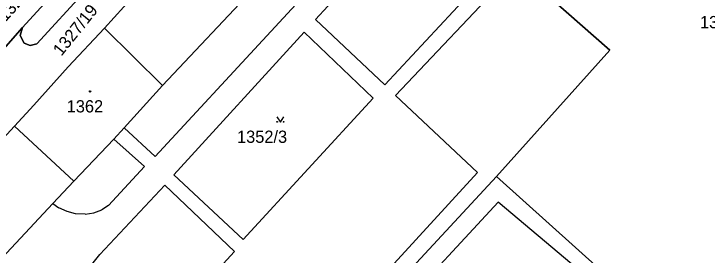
# Model space of a CAD drawing. Extents: x -598934 to -598196, y -1162208 to -1161502.
# Drawn here: x -598541.5 to -598445.3, y -1161757.9 to -1161724.5 of the extents above; entities that cross this region are included whole.
import ezdxf

# ---------------------------------------------------------------- set-up
doc = ezdxf.new("R2010")
doc.units = 0
for name, color, linetype in [('KN_CAR_KR', 7, 'Continuous'), ('KN_KULTURY', 7, 'Continuous'), ('KN_PARC_CIS_POZ', 7, 'Continuous'), ('KN_PARC_CIS_STAV', 7, 'Continuous'), ('KN_PARC_PLOCHA', 7, 'Continuous'), ('parcely_l', 7, 'Continuous')]:
    doc.layers.add(name, color=color, linetype=linetype)

msp = doc.modelspace()

# ---------------------------------------------------------------- linework, layer by layer
at = {"layer": 'KN_CAR_KR'}
for points in [[(-598490.92, -1161710.74), (-598521.91, -1161744.24)], [(-598499.66, -1161725.25), (-598487.64, -1161712.22)], [(-598474.84, -1161718), (-598490.01, -1161734.3)], [(-598472.67, -1161718.98), (-598488.52, -1161735.77)], [(-598490.01, -1161734.3), (-598499.66, -1161725.25)], [(-598519.32, -1161746.77), (-598501.23, -1161727.01)], [(-598501.23, -1161727.01), (-598491.63, -1161736.13)], [(-598491.63, -1161736.13), (-598509.7, -1161755.77)], [(-598488.52, -1161735.77), (-598477.15, -1161746.44)], [(-598521.91, -1161744.24), (-598526.22, -1161740.28)], [(-598527.64, -1161741.82), (-598523.4, -1161745.65)], [(-598523.4, -1161745.65), (-598528.36, -1161751.05)], [(-598509.7, -1161755.77), (-598519.32, -1161746.77)], [(-598477.15, -1161746.44), (-598498.32, -1161769.54)], [(-598529.59, -1161757.86), (-598520.58, -1161748.21)], [(-598520.58, -1161748.21), (-598510.88, -1161757.4)], [(-598536.13, -1161750.75), (-598535.29, -1161751.36)], [(-598474.27, -1161750.6), (-598503.05, -1161781.64)], [(-598445.66, -1161774.67), (-598474.27, -1161750.6)], [(-598534.14, -1161751.89), (-598535.29, -1161751.36)], [(-598530.41, -1161752.04), (-598529.32, -1161751.63)], [(-598528.36, -1161751.05), (-598529.32, -1161751.63)], [(-598532.95, -1161752.18), (-598534.14, -1161751.89)], [(-598531.6, -1161752.22), (-598532.95, -1161752.18)], [(-598531.6, -1161752.22), (-598530.41, -1161752.04)], [(-598510.88, -1161757.4), (-598525.11, -1161772.86)], [(-598531.06, -1161759.7), (-598529.59, -1161757.86)]]:
    msp.add_lwpolyline(points, dxfattribs=at)
at = {"layer": 'KN_KULTURY'}
msp.add_lwpolyline([(-598505.022, -1161738.732), (-598504.522, -1161739.482), (-598504.022, -1161738.732)], dxfattribs=at)
for centre, radius in [((-598530.94, -1161735.21), 0.09), ((-598530.94, -1161735.21), 0.0398), ((-598504.972, -1161739.431), 0.05), ((-598504.073, -1161739.431), 0.05)]:
    msp.add_circle(centre, radius, dxfattribs=at)
at = {"layer": 'KN_PARC_PLOCHA'}
for points in [[(-598444.82, -1161773.72), (-598474.53, -1161747.01), (-598458.77, -1161729.49), (-598468.63, -1161720.8), (-598458.45, -1161708.36), (-598488.05, -1161680.21), (-598492.06, -1161676.4), (-598438.63, -1161618.4)], [(-598545.62, -1161732.34), (-598540.3, -1161726.37), (-598540.65, -1161727.46), (-598540.1, -1161728.5), (-598539.25, -1161728.86), (-598538.31, -1161728.62), (-598518.22, -1161706.64)], [(-598526.27, -1161723.47), (-598528.95, -1161726.46), (-598534, -1161731.8), (-598538.76, -1161737.11), (-598541.41, -1161740.03), (-598546.27, -1161745.25)]]:
    msp.add_lwpolyline(points, dxfattribs=at)
for points in [[(-598515.78, -1161699.51), (-598520.62, -1161704.8), (-598540.3, -1161726.37), (-598545.62, -1161732.34), (-598551.22, -1161738.78), (-598552.06, -1161740.1), (-598557.21, -1161749.89), (-598557.79, -1161750.75), (-598560.03, -1161753.34), (-598567, -1161747.08), (-598547.88, -1161725.12), (-598521.97, -1161696.72)], [(-598540.3, -1161726.37), (-598520.62, -1161704.8), (-598519.56, -1161704.29), (-598518.51, -1161704.67), (-598518.05, -1161705.51), (-598518.22, -1161706.64), (-598538.31, -1161728.62), (-598539.25, -1161728.86), (-598540.1, -1161728.5), (-598540.65, -1161727.46)], [(-598468.63, -1161720.8), (-598458.77, -1161729.49), (-598474.53, -1161747.01), (-598505.54, -1161780.43), (-598505.91, -1161780.84), (-598507.88, -1161780.28), (-598515.19, -1161778.23), (-598542.18, -1161767.07), (-598540.95, -1161765.46), (-598543.04, -1161763.56), (-598545.78, -1161761.07), (-598536.13, -1161750.75), (-598533.19, -1161747.65), (-598527.64, -1161741.82), (-598526.22, -1161740.28), (-598520.88, -1161734.41), (-598507.87, -1161720.56), (-598509.16, -1161719.36), (-598497.98, -1161707.55), (-598490.92, -1161710.74), (-598487.64, -1161712.22), (-598474.84, -1161718), (-598472.67, -1161718.98)], [(-598509.16, -1161719.36), (-598507.87, -1161720.56), (-598520.88, -1161734.41), (-598528.95, -1161726.46), (-598526.27, -1161723.47), (-598516.27, -1161712.67)], [(-598520.88, -1161734.41), (-598526.22, -1161740.28), (-598527.64, -1161741.82), (-598533.19, -1161747.65), (-598541.41, -1161740.03), (-598538.76, -1161737.11), (-598534, -1161731.8), (-598528.95, -1161726.46)], [(-598533.19, -1161747.65), (-598536.13, -1161750.75), (-598545.78, -1161761.07), (-598554.08, -1161753.52), (-598551.27, -1161750.58), (-598546.27, -1161745.25), (-598541.41, -1161740.03)], [(-598444.82, -1161773.72), (-598445.66, -1161774.67), (-598460.51, -1161792.71), (-598471.76, -1161789.95), (-598474.37, -1161787.83), (-598477.08, -1161785.67), (-598479.63, -1161783.63), (-598482.3, -1161781.51), (-598484.93, -1161779.4), (-598487.57, -1161777.27), (-598490.17, -1161775.1), (-598493.4, -1161779.13), (-598496.93, -1161783.36), (-598503.05, -1161781.64), (-598505.91, -1161780.84), (-598505.54, -1161780.43), (-598474.53, -1161747.01)]]:
    msp.add_lwpolyline(points, close=True, dxfattribs=at)
at = {"layer": 'parcely_l'}
for points in [[(-598520.62, -1161704.8), (-598519.56, -1161704.29), (-598518.51, -1161704.67), (-598518.05, -1161705.51), (-598518.22, -1161706.64), (-598538.31, -1161728.62), (-598539.25, -1161728.86), (-598540.1, -1161728.5), (-598540.65, -1161727.46), (-598540.3, -1161726.37)], [(-598540.3, -1161726.37), (-598520.62, -1161704.8)], [(-598528.95, -1161726.46), (-598526.27, -1161723.47), (-598516.27, -1161712.67)], [(-598509.16, -1161719.36), (-598507.87, -1161720.56), (-598520.88, -1161734.41)], [(-598468.63, -1161720.8), (-598458.77, -1161729.49), (-598474.53, -1161747.01)], [(-598545.62, -1161732.34), (-598540.3, -1161726.37)], [(-598541.41, -1161740.03), (-598538.76, -1161737.11), (-598534, -1161731.8), (-598528.95, -1161726.46)], [(-598520.88, -1161734.41), (-598528.95, -1161726.46)], [(-598520.88, -1161734.41), (-598526.22, -1161740.28), (-598527.64, -1161741.82), (-598533.19, -1161747.65)], [(-598545.78, -1161761.07), (-598554.08, -1161753.52), (-598551.27, -1161750.58), (-598546.27, -1161745.25), (-598541.41, -1161740.03)], [(-598541.41, -1161740.03), (-598533.19, -1161747.65)], [(-598533.19, -1161747.65), (-598536.13, -1161750.75), (-598545.78, -1161761.07)], [(-598505.91, -1161780.84), (-598505.54, -1161780.43), (-598474.53, -1161747.01)], [(-598474.53, -1161747.01), (-598444.82, -1161773.72)]]:
    msp.add_lwpolyline(points, dxfattribs=at)

# ---------------------------------------------------------------- texts
at = {"layer": 'KN_PARC_CIS_POZ'}
for s, rotation, p in [('1327/112', 48.09007, (-598542.663, -1161725.63)), ('1327/19', 51.13446, (-598534.919, -1161730.406))]:
    msp.add_text(s, height=1.7, rotation=rotation, dxfattribs=at).set_placement(p)
msp.add_text('1352/3', height=1.7, dxfattribs=at).set_placement((-598510.537, -1161742.35))
at = {"layer": 'KN_PARC_CIS_STAV'}
for s, p in [('1358/1', (-598446.272, -1161726.45)), ('1362', (-598534.182, -1161738.13))]:
    msp.add_text(s, height=1.7, dxfattribs=at).set_placement(p)

doc.saveas('drawing.dxf')
